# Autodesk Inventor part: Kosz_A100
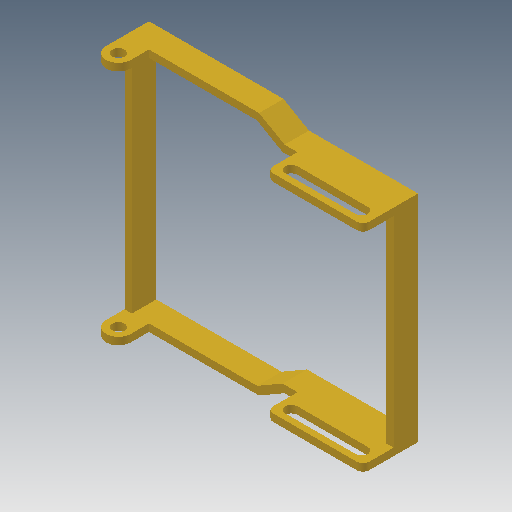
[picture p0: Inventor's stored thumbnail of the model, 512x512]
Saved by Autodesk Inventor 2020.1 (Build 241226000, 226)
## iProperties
Created: 2006-06
Part Number: Kosz_A100
Document SubType Name: Modeling
Designer: F.Stasiak
Density: 1 g/cm^3
Material: Ogólny
Appearance: Żółty (ciemny)
Manager: www.cadconsulting.pl
Company: Fabian Stasiak CAD Consulting
Author: F.Stasiak
Subject: Zbiór ćwiczeń. Autodesk Inventor 2020. Kurs podstawowy
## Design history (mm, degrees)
sketch "Szkic1"
  geometry: L1 (0, 500)-(550, 500); L2 (1100, 440)-(1100, -440); L3 (550, -500)-(0, -500); L4 (0, -500)-(0, 500); L5 (645.885, 410)-(1070, 410); L6 (1070, 410)-(1070, -410); L7 (1070, -410)-(645.885, -410); L8 (550, 500)-(653.923, 440); L9 (653.923, 440)-(1100, 440); L10 (550, -500)-(653.923, -440); L11 (653.923, -440)-(1100, -440); L12 (30, -470)-(30, 470); L13 (30, 470)-(541.962, 470); L14 (541.962, 470)-(645.885, 410); L15 (30, -470)-(541.962, -470); L16 (541.962, -470)-(645.885, -410); 2 further points
  constraints: 32 end point, 5 parallel, 4 perpendicular, 1 coincident, 1 horizontal, 1 midpoint, 1 other
  dimensions: "d0" = 1000 distance of L3.end L1.start; "d23" = 30 distance between parallel lines of L2 L6; "d24" = 90 distance between parallel lines of L1 L5; "d25" = 90 distance between parallel lines of L3 L7 (= d24); "d26" = 1100 distance between parallel lines of L2 L4; "d27" = 30 distance between parallel lines of L1 L13 (= d23); "d28" = 30 distance between parallel lines of L3 L15 (= d27); "d29" = 30 distance between parallel lines of L4 L12 (= d28); "d30" = 550 distance of L3.start L3.end; "d34" = 30 distance between parallel lines of L7 L11 (= d23); "d35" = 30 distance between parallel lines of L16 L10 (= d36); "d36" = 30 distance between parallel lines of L9 L5 (= d23); "d37" = 150 deg angle of L14 L13; "d38" = 150 deg angle of L16 L15 (= d37)
extrude "Wyciągnięcie proste1" new body sketch "Szkic1" distance "d3" = 200; taper "d4" = 0 deg
sketch "Szkic2"
  geometry: L1 (1100, 200)-(0, 200) reference; L2 (0, 200)-(0, 275); L3 (100, 275)-(100, 200); C1 r 25 at (50, 275); A1 r 50 centre (50, 275) between (100, 275) and (0, 275)
  constraints: 4 end point, 2 centre point, 2 perpendicular, 2 point on circle, 2 tangent, 1 coincident, 1 point on line
  dimensions: "d5" = 50 diameter of C1; "d6" = 50 radius of A1 (= d5); "d7" = 75 distance of L1.end L2.end (= 1.5 x d5)
extrude "Wyciągnięcie proste2" join sketch "Szkic2" distance "d8" = 30; taper "d9" = 0 deg
sketch "Szkic6"
  geometry: L1 (-312.893, -50)-(-25.064, -50); L2 (-25.064, -100)-(-312.893, -100); L3 (-416.077, 0)-(30, 0) reference; L4 (30, 0)-(30, -125); L5 (30, -125)-(-362.893, -125); L6 (-362.893, -125)-(-362.893, 0); C1 r 25 at (-25.064, -75) reference; C2 r 25 at (-312.893, -75) reference; A1 r 25 centre (-25.064, -75) between (-25.064, -100) and (-25.064, -50); A2 r 25 centre (-312.893, -75) between (-312.893, -50) and (-312.893, -100)
  constraints: 10 end point, 4 concentric, 4 point on circle, 3 perpendicular, 3 tangent, 2 centre point, 1 horizontal, 1 point on line
  dimensions: "d39" = 25 distance between parallel lines of L2 L5; "d40" = 50 distance from line of C2.centre L6
extrude "Wyciągnięcie proste6" join sketch "Szkic6" stored distance "d41" = 10; taper "d42" = 0 deg
fillet "Zaokrąglenie2" dims "d43" = 25
mirror "Lustro2"
node "Płaszczyzna konstrukcyjna2"
feature "Przesunięcie powierzchni1" dims "d44" = 100
node "Bryła1"
node "Korpusy bryłowe"
node "Korpusy powierzchniowe"
node "Odniesienie7"
node "Odniesienie8"
